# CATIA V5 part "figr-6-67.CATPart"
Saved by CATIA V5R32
Part number: Part2
Bounding box of the stored display mesh (mm): x -48.023 to 47.984, y -42.839 to 53.196, z 0 to 122.21
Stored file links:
  D:\PROJECTS\Project 2022\CATIA V5 6R 2022\Resources\Part Files\c06_catia_v5_6r2022_prt\figr-6-67.CATPart
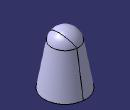
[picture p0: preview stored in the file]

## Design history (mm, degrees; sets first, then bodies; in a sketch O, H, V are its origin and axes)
Body1 (main body)
  Sketch1 on yz-plane, origin (0, 0, 0), H (0, 1, 0), V (0, 0, 1)
    axis line L1 (-55.8323, 90.9269) -> (61.0167, 90.9269)
    arc A1 centre (5.1844, 90.9269) radius 31.5054 from (36.6898, 90.9269) to (-26.3209, 90.9269) ccw
    point P3 (5.1844, 90.9269)
    point P4 (36.6898, 90.9269)
    point P5 (-26.3209, 90.9269)
    line L2 (-26.3209, 90.9269) -> (36.6898, 90.9269)
    horizontal: L1 H, L2 H
    coincidence: P3 L1, P4 L1, P5 L1
  Shaft1: profile Sketch1, axis Sketch1.L1, angle 360
  Draft1: Angle 10, Parting xy-plane, PullDir (0, 0, 1), SupportToDraft face of Shaft1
